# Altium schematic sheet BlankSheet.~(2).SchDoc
size 431 x 279 mm; Date: Not shown in title block; ApprovedBy: Not shown in title block; CheckedBy: Not shown in title block; Author: Not shown in title block; CompanyName: Not shown in title block; Engineer: Not shown in title block; Organization: Not shown in title block; Address1: Not shown in title block; Address2: Not shown in title block; Address3: Not shown in title block; Address4: Not shown in title block; DocumentNumber: 1; Revision: Use project parameter SCH_Rev; SheetNumber: 2; SheetTotal: 3; PageSetup: Record=PageOptions¦CenterHorizontal=True¦CenterVertical=True¦PrintScale=0.64¦XCorrection=1.00¦YCorrection=1.00¦PrintKind=0¦BorderSize=5000000¦LeftOffset=0¦BottomOffset=0¦Orientation=2¦PaperLength=1000¦PaperWidth=1000¦Scale=100¦PaperSource=15¦PrintQuality=600¦MediaType=1¦DitherType=10¦PrintScaleMode=1¦PaperKind=Letter
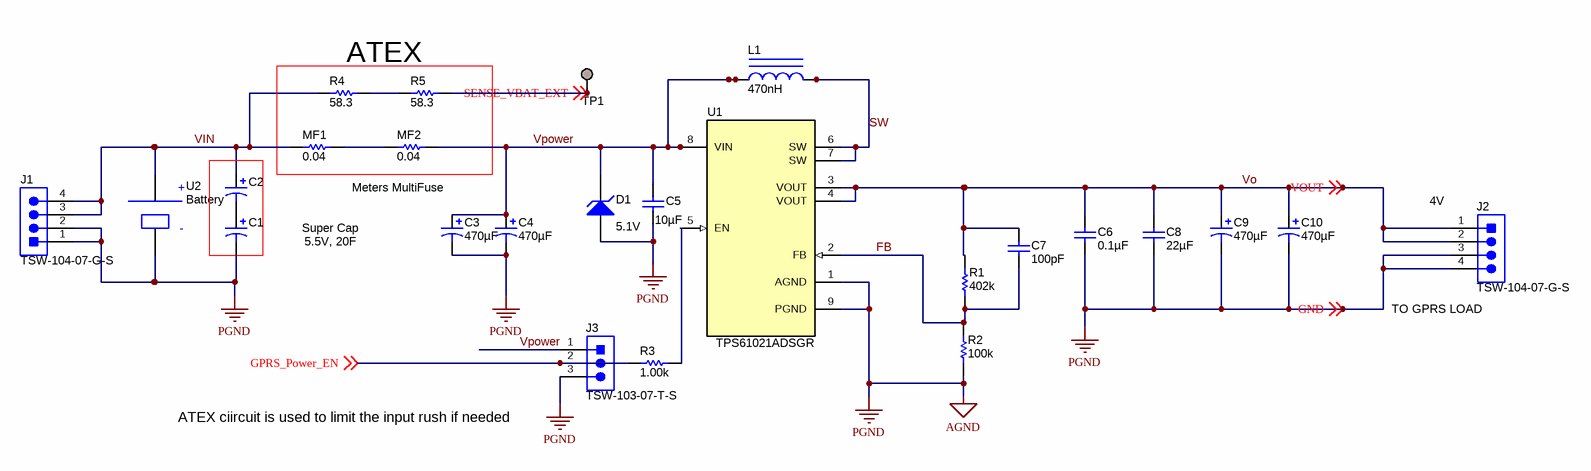
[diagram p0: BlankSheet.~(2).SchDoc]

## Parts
C1  EEU-FC1H222  [FC_1800x3550]  (value not drawn)
C2  EEU-FC1H222  [FC_1800x3550]  (value not drawn)
C3  ValueDisplayed: 470µF  [SEPC_C9]  (hidden comment: 6SEPC470MW)
C4  ValueDisplayed: 470µF  [SEPC_C9]  (hidden comment: 6SEPC470MW)
C5  ValueDisplayed: 10µF  [0603]  (hidden comment: GRM188R60J106ME84)
C6  ValueDisplayed: 0.1µF  [0603]  (hidden comment: GRM188R71C104KA01D)
C7  ValueDisplayed: 100pF  [0201_033]  (hidden comment: C0603C0G1E101J030BA)
C8  ValueDisplayed: 22µF  [0603]  (hidden comment: C1608X5R0J226M080AC)
C9  ValueDisplayed: 470µF  [SEPC_C9]  (hidden comment: 6SEPC470MW)
C10  ValueDisplayed: 470µF  [SEPC_C9]  (hidden comment: 6SEPC470MW)
D1  value 5.1V  [SMB]  (hidden comment: 1SMB5918BT3G)
J1  TSW-104-07-G-S  [TSW-104-07-G-S]
J2  TSW-104-07-G-S  [TSW-104-07-G-S]
J3  TSW-103-07-T-S  [Samtec_TSW-103-07-T-S]
L1  ValueDisplayed: 470nH  [XFL4015]  (hidden comment: XFL4015-471MEC)
MF1  ValueDisplayed: 0.04  [2010]  (hidden comment: CSRN2010FK40L0)
MF2  ValueDisplayed: 0.04  [2010]  (hidden comment: CSRN2010FK40L0)
R1  ValueDisplayed: 402k  [0603]  (hidden comment: RC0603FR-07402KL)
R2  ValueDisplayed: 100k  [0603]  (hidden comment: CPF0603B100KE)
R3  ValueDisplayed: 1.00k  [0603]  (hidden comment: CRCW06031K00FKEA)
R4  ValueDisplayed: 58.3  [0603]  (hidden comment: RT0603BRD0758R3L)
R5  ValueDisplayed: 58.3  [0603]  (hidden comment: RT0603BRD0758R3L)
TP1  Suggest using a net name here  [Keystone1502-2]  (value not drawn)
U1  TPS61021ADSGR  [DSG0008A]
U2  Battery

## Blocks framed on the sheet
ATEX: MF1 MF2 R4 R5

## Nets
AGND: C1.2(-) C3.2(-) C4.2(-) C5.2 C6.2 C8.2 C9.2(-) C10.2(-) D1.2(A) J1.1 J1.2 J2.3 J2.4 J3.3 R2.1 U1.1(AGND) U1.9(PGND) U2.2 ; off-sheet GND  [also labelled GND, PGND]
FB: C7.2 R1.1 R2.2 U1.2(FB)
GPRS_Power_EN: J3.2 R3.1 ; off-sheet GPRS_Power_EN
SENSE_VBAT_EXT: R5.2 TP1.1 ; off-sheet SENSE_VBAT_EXT
SW: L1.2 U1.6(SW) U1.7(SW)
VIN: C2.1(+) J1.3 J1.4 MF1.1 R4.1 U2.1
Vo: C6.1 C7.1 C8.1 C9.1(+) C10.1(+) J2.1 J2.2 R1.2 U1.3(VOUT) U1.4(VOUT) ; off-sheet VOUT  [also labelled VOUT]
Vpower: C3.1(+) C4.1(+) C5.1 D1.1(K) J3.1 L1.1 MF2.2 U1.8(VIN)
NetC1_1: C1.1(+) C2.2(-)
NetMF1_2: MF1.2 MF2.1
NetR3_2: R3.2 U1.5(EN)
NetR4_2: R4.2 R5.1

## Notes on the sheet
- Meters MultiFuse
- (near J2) 4V
- Super Cap
- 5.5V, 20F
- (near J2) TO GPRS LOAD
- (near J3) ATEX ciircuit is used to limit the input rush if needed

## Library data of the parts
C1 = EEU-FC1H222: KAMAP, 2.7V, 40F; Manufacturer: Panasonic; Polarized: Y; CompType: Capacitor; Value: 2200uF; ValueDisplayed: 2200µF; U/M: EA; Cap_F: 0.0022; Tolerance_%: 20; Value1: 0.023 ohm; VDC_V: 50; Value2: 50V; ESR_ohm: 0.023; IRMS_A: 3.1; TaMin_C: -55; TaMax_C: 105; Cap_Case: 18x35.5mm; AEC Category: Q200; AEC Grade: 2
C2 = EEU-FC1H222: KAMAP 2.7V, 40F; Manufacturer: Panasonic; Polarized: Y; CompType: Capacitor; Value: 2200uF; ValueDisplayed: 2200µF; U/M: EA; Cap_F: 0.0022; Tolerance_%: 20; Value1: 0.023 ohm; VDC_V: 50; Value2: 50V; ESR_ohm: 0.023; IRMS_A: 3.1; TaMin_C: -55; TaMax_C: 105; Cap_Case: 18x35.5mm; AEC Category: Q200; AEC Grade: 2
C3 C4 C9 C10 = 6SEPC470MW: CAP, AL, 470 µF, 6.3 V, +/- 20%, 0.007 ohm, TH; Manufacturer: Panasonic; Polarized: Y; CompType: Capacitor; Value: 470uF; U/M: EA; Cap_F: 0.00047; Tolerance_%: 20; VDC_V: 6.3; Value2: 6.3V; ESR_ohm: 0.007; IRMS_A: 5.6; TaMin_C: -55; TaMax_C: 105; Cap_Case: 6.3x9; AEC Category: Q200
C5 = GRM188R60J106ME84: CAP, CERM, 10 µF, 6.3 V, +/- 20%, X5R, 0603; Manufacturer: MuRata; Polarized: N; CompType: Capacitor; Value: 10uF; U/M: EA; Cap_F: 0.00001; Tolerance_%: 20; Value1: Unknown; VDC_V: 6.3; Value2: 6.3V; TaMin_C: -55; TaMax_C: 85
C6 = GRM188R71C104KA01D: CAP, CERM, 0.1 µF, 16 V, +/- 10%, X7R, 0603; Manufacturer: MuRata; Polarized: N; CompType: Capacitor; Value: 0.1uF; U/M: EA; Cap_F: 0.0000001; Tolerance_%: 10; Value1: Unknown; VDC_V: 16; Value2: 16V; TaMin_C: -55; TaMax_C: 125
C7 = C0603C0G1E101J030BA: CAP, CERM, 100 pF, 25 V, +/- 5%, C0G/NP0, 0201; Manufacturer: TDK; Polarized: N; CompType: Capacitor; Value: 100pF; U/M: EA; Cap_F: 0.0000000001; Tolerance_%: 5; Value1: Unknown; VDC_V: 25; Value2: 25V; TaMin_C: -55; TaMax_C: 125; Cap_Case: 0201; AEC Category: Q200
C8 = C1608X5R0J226M080AC: CAP, CERM, 22 µF, 6.3 V, +/- 20%, X5R, 0603; Manufacturer: TDK; Polarized: N; CompType: Capacitor; Value: 22uF; U/M: EA; Cap_F: 0.000022; Tolerance_%: 20; Value1: Unknown; VDC_V: 6.3; Value2: 6.3V; TaMin_C: -55; TaMax_C: 85; AEC Category: Q200
D1 = 1SMB5918BT3G: Diode, Zener, 5.1 V, 550 mW, SMB; Manufacturer: ON Semiconductor; SymbolCreator: a0412235; U/M: EA; Power_W: 0.55; Vz_V: 5.1; Value1: 0.55W; RJA_CperW: 226; AEC Category: Q101
J1 J2 = TSW-104-07-G-S: Header, 100mil, 4x1, Gold, TH; Manufacturer: Samtec; SymbolCreator: a0412235; Pitch_mm: 2.54; Gender: Male; Shrouded: N; Row_Count: 1; Current_A: 6.3; Voltage_V: 550; Cert_CSA: Y
J3 = TSW-103-07-T-S: Header, 2.54 mm, 3x1, Tin, TH; Manufacturer: Samtec; SymbolCreator: a0799628; Pitch_mm: 2.54; Gender: Male; Shrouded: N; Row_Count: 1; Current_A: 6.3; Voltage_V: 550; Cert_CSA: Y
L1 = XFL4015-471MEC: Inductor, Shielded, Composite, 470 nH, 3.5 A, 0.0076 ohm, SMD; Manufacturer: Coilcraft; Value: 470nH; Ind_H: 470.0E-9; Imax_A: 3.5; Irms: 9.1A @ 20C rise; Isat: 3.5A @ 10% inductance drop; DCR_ohm: 0.0076; Value2: 3.5A; AEC Category: Q200
MF1 MF2 = CSRN2010FK40L0: RES, 0.04, 1%, 1 W, 2010; Manufacturer: Stackpole Electronics Inc; CompType: Resistor; Value: 0.04; Value_Code: R040; Tolerance_%: 1; Value2: 1W; TempCo: 250 ppm/C; U/M: EA; AEC Category: Q200
R1 = RC0603FR-07402KL: RES, 402 k, 1%, 0.1 W, 0603; Manufacturer: Yageo America; CompType: Resistor; Value: 402k; Res_ohm: 402000; Tolerance_%: 1; Power_W: 0.1; Value2: 0.1W; VDC_V: 150; TempCo: 200 ppm/C; EIA_Code: E96; U/M: EA; AEC Category: Q200
R2 = CPF0603B100KE: RES, 100 k, 0.1%, 0.063 W, 0603; Manufacturer: TE Connectivity; CompType: Resistor; Value: 100k; Res_ohm: 100000; Tolerance_%: 0.1; Power_W: 0.063; Value2: 0.063W; VDC_V: 50; TempCo: 25 ppm/C; EIA_Code: E192; U/M: EA
R3 = CRCW06031K00FKEA: RES, 1.00 k, 1%, 0.1 W, 0603; Manufacturer: Vishay-Dale; CompType: Resistor; Value: 1.00k; Res_ohm: 1000; Value_Code: 1k00; Tolerance_%: 1; Power_W: 0.1; Value2: 0.1W; VDC_V: 75; TempCo: 100 ppm/C; EIA_Code: E96; U/M: EA; AEC Category: Q200
R4 R5 = RT0603BRD0758R3L: RES, 58.3, 0.1%, 0.1 W, 0603; Manufacturer: Yageo America; CompType: Resistor; Value: 58.3; Value_Code: 58R3; Tolerance_%: 0.1; Value2: 0.1W; VDC_V: 75; TempCo: 25 ppm/C; EIA_Code: E192; U/M: EA; AEC Category: Q200
TP1 = 1502-2: Terminal, Turret, TH, Double; Manufacturer: Keystone; CompType: Turret Terminal
U1 = TPS61021DSGR: 3-A BOOST CONVERTER WITH 0.5V ULTRA-LOW INPUT VOLTAGE, DSG0008A; Alternate PartNumber: TPS61021DSGT; Manufacturer: Texas Instruments; SymbolCreator: Altium; CompType: IC; U/M: EA
U2 = Component_1: Manufacturer: Used in BOM report; SymbolVersion: use current date i.e. 2008-05-20; SymbolCreator: Use a-id; CompType: Used in some BOM reports.  Useful for finding later.; U/M: EA, IN, or GM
